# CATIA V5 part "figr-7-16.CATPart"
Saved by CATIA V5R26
Part number: Part2
Bounding box of the stored display mesh (mm): x -50 to 50, y -65 to 65, z 0 to 28
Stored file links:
  D:\_Deepak\CATIA\CATIA V5-6R2016_Deepak\Resources\Part files\Partfiles\c07_catia_v5_6r2016_prt\figr-7-16.CATPart
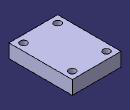
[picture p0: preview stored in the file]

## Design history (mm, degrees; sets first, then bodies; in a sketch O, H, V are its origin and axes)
Body1 (main body)
  Sketch1 on xy-plane, origin (0, 0, 0), H (1, 0, 0), V (0, 1, 0)
    line L1 (-50, 65) -> (50, 65)
    line L2 (50, 65) -> (50, -65)
    line L3 (50, -65) -> (-50, -65)
    line L4 (-50, -65) -> (-50, 65)
    axis line L5 (50, -65) -> (-50, 65)
    length L3 = 100
    length L2 = 130
    horizontal: L1 H, L3 H
    vertical: L2 V, L4 V
    midpoint: O L5
  Pad1: profile Sketch1, direction (0, 0, 1), length 28
  Sketch2 on face of Pad1, origin (25.9302, -33.7092, 28), H (1, 0, 0), V (0, 1, 0)
    point P1 (9.0698, -16.2908)
    reference projected line E1 (-75.9302, -31.2908) -> (24.0698, -31.2908) from edge [face of Pad1 | face of Pad1]
    reference projected line E2 (24.0698, -31.2908) -> (24.0698, 98.7092) from edge [face of Pad1 | face of Pad1]
    distance P1 E1 = 15
    distance P1 E2 = 15
  Hole1: placed by Sketch2, at (35, -50, 28) direction (0, 0, -1), diameter 14, through (limit type 3)
  RectPattern1: of Hole1, direction 1 instances 2, spacing 100, along edge [face of Pad1 | face of Pad1], direction 2 instances 2, spacing 70, along edge [face of Pad1 | face of Pad1]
